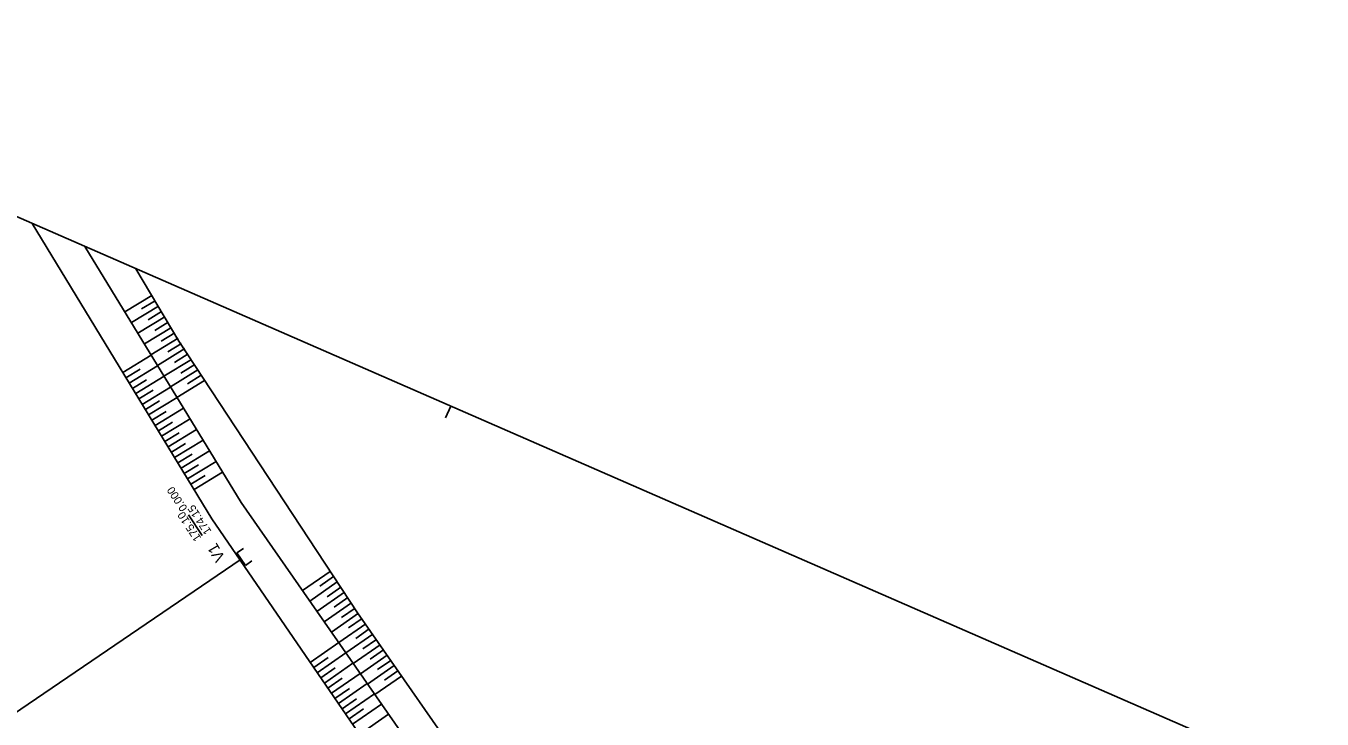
# Model space of a CAD drawing. Extents: x -574526 to -573537, y -1188297 to -1187280.
# Drawn here: x -573739.4 to -573537, y -1187388.1 to -1187279.8 of the extents above; entities that cross this region are included whole.
import ezdxf

# ---------------------------------------------------------------- set-up
doc = ezdxf.new("R2010")
doc.units = 0
for name, color, linetype in [('Vrstva 10', 7, 'Continuous'), ('Vrstva 13', 7, 'Continuous'), ('Vrstva 18', 7, 'Continuous'), ('Vrstva 2', 7, 'Continuous'), ('Vrstva 63', 7, 'Continuous'), ('Vrstva 8', 7, 'Continuous')]:
    doc.layers.add(name, color=color, linetype=linetype)

# ---------------------------------------------------------------- blocks, each defined once
blk = doc.blocks.new('200')
at = {"layer": 'Vrstva 63'}
blk.add_lwpolyline([(0, 0), (210, 0), (210, 297), (0, 297), (0, 0)], close=True, dxfattribs=at)

msp = doc.modelspace()

# ---------------------------------------------------------------- linework, layer by layer
at = {"layer": 'Vrstva 10'}
for p, q in [((-573719.8, -1187321.94), (-573724, -1187324.5)), ((-573718.76, -1187323.6), (-573722.98, -1187326.17)), ((-573719.28, -1187322.77), (-573721.38, -1187324.05)), ((-573718.25, -1187324.43), (-573720.36, -1187325.72)), ((-573717.73, -1187325.27), (-573721.96, -1187327.84)), ((-573717.21, -1187326.1), (-573719.33, -1187327.39)), ((-573716.7, -1187326.93), (-573720.94, -1187329.52)), ((-573716.18, -1187327.76), (-573718.31, -1187329.06)), ((-573715.66, -1187328.59), (-573719.92, -1187331.19)), ((-573714.63, -1187330.25), (-573718.9, -1187332.86)), ((-573715.15, -1187329.42), (-573717.28, -1187330.72)), ((-573724.33, -1187333.95), (-573719.89, -1187331.25)), ((-573713.6, -1187331.92), (-573717.89, -1187334.53)), ((-573714.12, -1187331.08), (-573716.26, -1187332.39)), ((-573723.82, -1187334.79), (-573721.6, -1187333.43)), ((-573723.31, -1187335.62), (-573718.87, -1187332.91)), ((-573722.3, -1187337.28), (-573717.86, -1187334.57)), ((-573712.57, -1187333.58), (-573716.87, -1187336.2)), ((-573713.08, -1187332.75), (-573715.23, -1187334.06)), ((-573712.05, -1187334.41), (-573714.2, -1187335.72)), ((-573722.81, -1187336.45), (-573720.59, -1187335.1)), ((-573721.29, -1187338.95), (-573716.85, -1187336.24)), ((-573711.53, -1187335.24), (-573715.85, -1187337.87)), ((-573721.8, -1187338.11), (-573719.57, -1187336.76)), ((-573720.78, -1187339.78), (-573718.56, -1187338.42)), ((-573720.28, -1187340.61), (-573715.83, -1187337.9)), ((-573719.77, -1187341.44), (-573717.55, -1187340.09)), ((-573719.26, -1187342.27), (-573714.82, -1187339.56)), ((-573718.76, -1187343.11), (-573716.53, -1187341.75)), ((-573718.25, -1187343.94), (-573713.8, -1187341.22)), ((-573717.75, -1187344.77), (-573715.52, -1187343.41)), ((-573717.24, -1187345.6), (-573712.79, -1187342.89)), ((-573716.23, -1187347.27), (-573711.78, -1187344.55)), ((-573716.73, -1187346.43), (-573714.51, -1187345.08)), ((-573715.72, -1187348.1), (-573713.5, -1187346.74)), ((-573715.22, -1187348.93), (-573710.76, -1187346.21)), ((-573714.71, -1187349.76), (-573712.48, -1187348.4)), ((-573714.2, -1187350.59), (-573709.75, -1187347.88)), ((-573713.7, -1187351.43), (-573711.47, -1187350.07)), ((-573713.19, -1187352.26), (-573708.73, -1187349.54)), ((-573691.93, -1187365.05), (-573696.25, -1187368.06)), ((-573690.82, -1187366.69), (-573695.12, -1187369.68)), ((-573691.38, -1187365.87), (-573693.53, -1187367.37)), ((-573689.71, -1187368.32), (-573693.99, -1187371.3)), ((-573690.26, -1187367.5), (-573692.41, -1187369)), ((-573688.59, -1187369.96), (-573692.86, -1187372.93)), ((-573689.15, -1187369.14), (-573691.29, -1187370.63)), ((-573688.04, -1187370.77), (-573690.16, -1187372.26)), ((-573687.48, -1187371.59), (-573691.73, -1187374.55)), ((-573686.92, -1187372.41), (-573689.04, -1187373.89)), ((-573686.36, -1187373.23), (-573690.59, -1187376.17)), ((-573685.25, -1187374.86), (-573689.46, -1187377.8)), ((-573685.81, -1187374.05), (-573687.92, -1187375.52)), ((-573695.03, -1187379.28), (-573690.59, -1187376.18)), ((-573684.14, -1187376.5), (-573688.33, -1187379.42)), ((-573684.69, -1187375.68), (-573686.8, -1187377.15)), ((-573694.48, -1187380.08), (-573692.25, -1187378.53)), ((-573693.93, -1187380.88), (-573689.47, -1187377.78)), ((-573683.02, -1187378.13), (-573687.2, -1187381.04)), ((-573683.58, -1187377.32), (-573685.67, -1187378.77)), ((-573682.47, -1187378.95), (-573684.55, -1187380.4)), ((-573693.37, -1187381.69), (-573691.15, -1187380.13)), ((-573692.82, -1187382.49), (-573688.36, -1187379.38)), ((-573691.72, -1187384.09), (-573687.25, -1187380.98)), ((-573681.91, -1187379.77), (-573686.07, -1187382.67)), ((-573681.35, -1187380.59), (-573683.43, -1187382.03)), ((-573692.27, -1187383.29), (-573690.04, -1187381.73)), ((-573690.62, -1187385.7), (-573686.14, -1187382.58)), ((-573680.8, -1187381.41), (-573684.94, -1187384.29)), ((-573691.17, -1187384.9), (-573688.93, -1187383.34)), ((-573690.07, -1187386.5), (-573687.83, -1187384.94)), ((-573689.52, -1187387.31), (-573685.02, -1187384.17)), ((-573688.97, -1187388.11), (-573686.72, -1187386.54)), ((-573688.42, -1187388.91), (-573683.91, -1187385.77)), ((-573687.32, -1187390.52), (-573682.8, -1187387.37))]:
    msp.add_line(p, q, dxfattribs=at)
for points in [[(-573738.48, -1187310.69), (-573710.41, -1187356.83), (-573646.2, -1187450.52), (-573611.14, -1187497.24), (-573589.12, -1187518.03)], [(-573587.08, -1187513.37), (-573604.17, -1187495.27), (-573639.07, -1187450.15), (-573705.83, -1187354.31), (-573730.22, -1187314.3)], [(-573584.16, -1187506.67), (-573598.73, -1187491.53), (-573630.67, -1187453.39), (-573687.67, -1187371.53), (-573715.57, -1187329.1), (-573722.26, -1187317.77)]]:
    msp.add_lwpolyline(points, dxfattribs=at)
at = {"layer": 'Vrstva 13'}
msp.add_line((-573711.91, -1187359.44), (-573714.06, -1187356.19), dxfattribs=at)
at = {"layer": 'Vrstva 2'}
msp.add_line((-573705.83, -1187363.12), (-573792.66, -1187422.28), dxfattribs=at)
at = {"layer": 'Vrstva 63'}
msp.add_line((-573673.1, -1187339.24), (-573673.9, -1187341.07), dxfattribs=at)
at = {"layer": 'Vrstva 8'}
for p, q in [((-573705.48, -1187361.45), (-573706.49, -1187362.14)), ((-573706.49, -1187362.14), (-573705.16, -1187364.11)), ((-573704.14, -1187363.42), (-573705.16, -1187364.11))]:
    msp.add_line(p, q, dxfattribs=at)

# ---------------------------------------------------------------- block references
at = {"layer": 'Vrstva 63', "xscale": 3.0000000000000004, "rotation": 66.41577100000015}
msp.add_blockref('200', (-573789.06, -1187976.03), dxfattribs=at)

# ---------------------------------------------------------------- texts
at = {"layer": 'Vrstva 13'}
for s, p in [('0.000', (-573714.16, -1187355.16)), ('174.15', (-573710.41, -1187358.78)), ('175.10', (-573712, -1187359.84))]:
    msp.add_text(s, height=1.25, rotation=123.5034, dxfattribs=at).set_placement(p)
at = {"layer": 'Vrstva 18'}
msp.add_text('V1', height=1.749, rotation=120.3291, dxfattribs=at).set_placement((-573708.26, -1187362.94))

doc.saveas('drawing.dxf')
